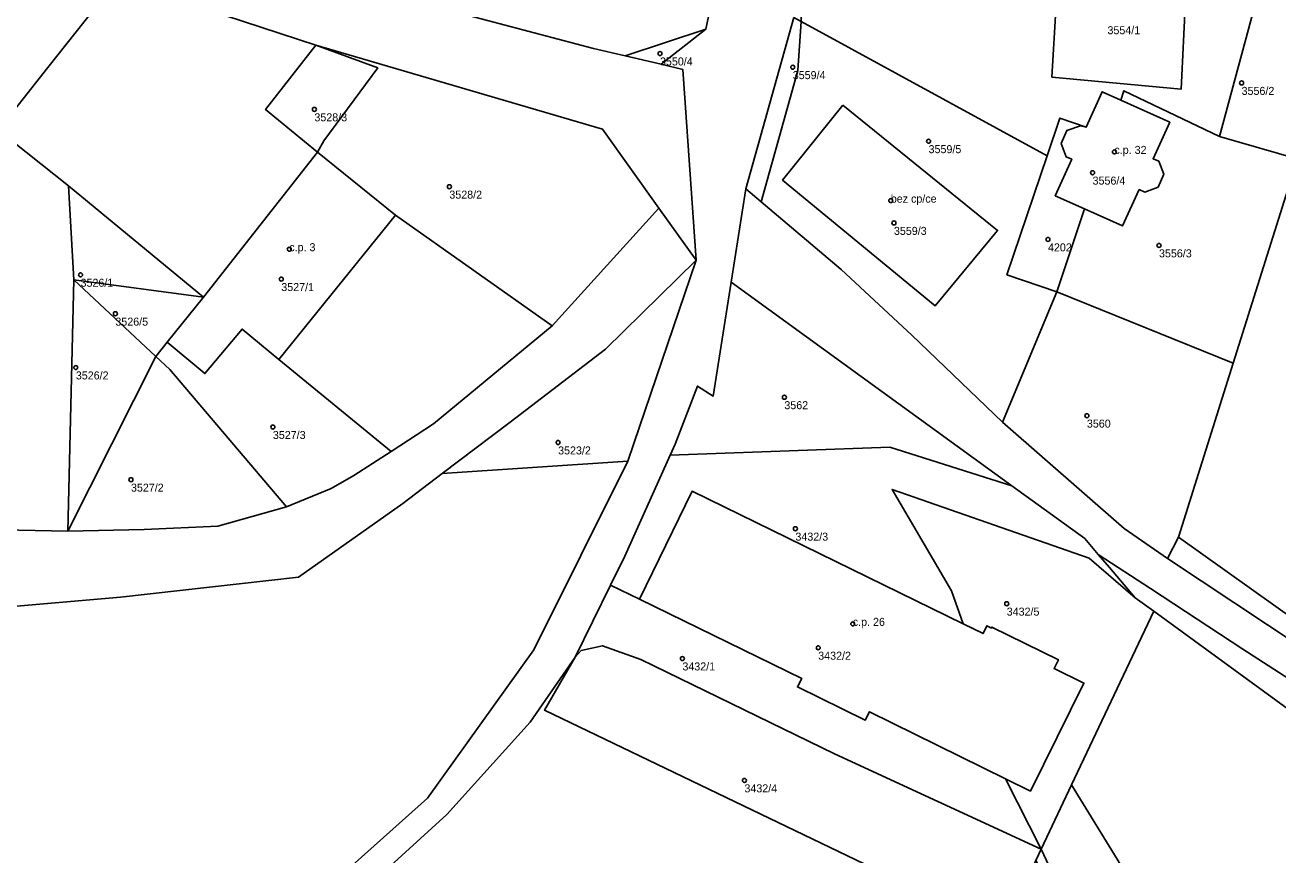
# Model space of a CAD drawing. Extents: x -878211 to -870363, y -1058464 to -1052522.
# Drawn here: x -876248.4 to -876091.8, y -1055083.2 to -1054979.5 of the extents above; entities that cross this region are included whole.
import ezdxf

# ---------------------------------------------------------------- set-up
doc = ezdxf.new("R2010")
doc.units = 0
for name, color, linetype in [('Vrstva 50', 7, 'Continuous'), ('Vrstva 51', 7, 'Continuous'), ('Vrstva 52', 7, 'Continuous')]:
    doc.layers.add(name, color=color, linetype=linetype)

msp = doc.modelspace()

# ---------------------------------------------------------------- linework, layer by layer
at = {"layer": 'Vrstva 50'}
for centre in [(-876169.04, -1054983.06994), (-876152.45, -1054984.77994), (-876096.37, -1054986.74994), (-876212.22, -1054990.04994), (-876135.48, -1054994.02994), (-876112.26, -1054995.35994), (-876114.99, -1054997.95994), (-876195.36, -1054999.70994), (-876140.2, -1055001.44994), (-876139.81, -1055004.23994), (-876120.56, -1055006.29994), (-876106.69, -1055007.04994), (-876215.36, -1055007.51994), (-876241.44, -1055010.71994), (-876216.36, -1055011.25994), (-876237.09, -1055015.57994), (-876242.03, -1055022.29994), (-876153.5, -1055026.01994), (-876115.7, -1055028.31994), (-876217.41, -1055029.73994), (-876181.77, -1055031.66994), (-876235.14, -1055036.31994), (-876152.12, -1055042.43994), (-876125.72, -1055051.80994), (-876144.95, -1055054.32994), (-876149.27, -1055057.31994), (-876166.24, -1055058.65994), (-876158.49, -1055073.88994)]:
    msp.add_circle(centre, 0.25, dxfattribs=at)
at = {"layer": 'Vrstva 51'}
for points in [[(-876192.82, -1054978.37), (-876177.34, -1054982.44), (-876173.38, -1054983.37), (-876163.32, -1054980.03), (-876160.81, -1054968.12), (-876164.19, -1054966.37), (-876185.22, -1054958.74), (-876186.64, -1054962)], [(-876111.56, -1054967.55), (-876117.63, -1054967.56), (-876121.09, -1054967.32), (-876123.64, -1054966.96), (-876133.24, -1054967.48), (-876126.34, -1054969.03), (-876126.76, -1054976.42), (-876119.52, -1054976.93), (-876120.07, -1054986.02), (-876103.91, -1054987.52), (-876103.39, -1054976.34), (-876104.13, -1054976.31), (-876104.06, -1054973.91), (-876109.76, -1054973.6), (-876109.46, -1054967.74)], [(-876230.61, -1055019.14), (-876225.89, -1055023.06), (-876221.26, -1055017.49), (-876216.66, -1055021.3), (-876202.64, -1055032.79), (-876197.32, -1055029.35), (-876182.5, -1055017.11), (-876202.1, -1055003.26), (-876211.84, -1054995.38), (-876218.33, -1054990.08), (-876212.05, -1054982.01), (-876236.87, -1054973.88), (-876237.48, -1054974.65), (-876245.51, -1054984.81), (-876251.72, -1054992.65), (-876242.95, -1054999.62), (-876226.09, -1055013.5)], [(-876089.29, -1054996.25), (-876083.43, -1054979.02), (-876094.37, -1054975.83), (-876099.15, -1054993.44)], [(-876152.32, -1054978.56), (-876158.32, -1054999.97), (-876156.39, -1055001.61), (-876151.83, -1054985.19), (-876151.42, -1054979.05)], [(-876163.32, -1054980.03), (-876173.38, -1054983.37), (-876168.91, -1054984.41)], [(-876126.23, -1055029.14), (-876119.47, -1055012.84), (-876125.7, -1055010.71), (-876120.67, -1054995.87), (-876151.42, -1054979.05), (-876151.83, -1054985.19), (-876156.39, -1055001.61), (-876146.41, -1055010.04), (-876137.56, -1055018.26)], [(-876212.05, -1054982.01), (-876218.33, -1054990.08), (-876211.84, -1054995.38), (-876211.03, -1054993.98), (-876204.31, -1054984.86)], [(-876204.31, -1054984.86), (-876211.03, -1054993.98), (-876211.84, -1054995.38), (-876202.1, -1055003.26), (-876182.5, -1055017.11), (-876169.19, -1055002.37), (-876176.22, -1054992.51), (-876212.05, -1054982.01)], [(-876097.42, -1055021.74), (-876104.26, -1055043.49), (-876053.74, -1055079.5), (-876016.38, -1055109.9), (-875979.71, -1055134.31), (-875976.33, -1055133.07), (-875966.79, -1055136.01), (-875949.8, -1055118.58), (-875906.55, -1055032.87), (-875978.7, -1054987.87), (-875998.96, -1054984.29), (-876051.39, -1054986.14), (-876052.15, -1054989.95), (-876052.67, -1054991.22), (-876056.06, -1054997.03), (-876063.41, -1055005.05), (-876067.92, -1055003.02), (-876087.78, -1054996.68), (-876089.29, -1054996.25), (-876090.8, -1055000.71)], [(-876115.77, -1054992.27), (-876116.51, -1054992.09), (-876118.19, -1054992.68), (-876118.91, -1054994.3), (-876118.29, -1054995.96), (-876117.6, -1054996.28), (-876119.66, -1055000.83), (-876116, -1055002.47), (-876111.23, -1055004.61), (-876109.15, -1055000.07), (-876108.47, -1055000.38), (-876106.81, -1054999.76), (-876106.08, -1054998.16), (-876106.73, -1054996.52), (-876107.42, -1054996.21), (-876105.35, -1054991.65), (-876111.46, -1054988.9), (-876113.8, -1054987.85)], [(-876116, -1055002.47), (-876119.47, -1055012.84), (-876097.42, -1055021.74), (-876090.8, -1055000.71), (-876089.29, -1054996.25), (-876099.15, -1054993.44), (-876111.07, -1054987.72), (-876111.46, -1054988.9), (-876105.35, -1054991.65), (-876107.42, -1054996.21), (-876106.73, -1054996.52), (-876106.08, -1054998.16), (-876106.81, -1054999.76), (-876108.47, -1055000.38), (-876109.15, -1055000.07), (-876111.23, -1055004.61)], [(-876146.18, -1054989.51), (-876153.73, -1054998.89), (-876134.65, -1055014.58), (-876126.85, -1055005.18)], [(-876146.18, -1054989.51), (-876126.85, -1055005.18), (-876134.65, -1055014.58), (-876153.73, -1054998.89)], [(-876125.7, -1055010.71), (-876119.47, -1055012.84), (-876116, -1055002.47), (-876119.66, -1055000.83), (-876117.6, -1054996.28), (-876118.29, -1054995.96), (-876118.91, -1054994.3), (-876118.19, -1054992.68), (-876116.51, -1054992.09), (-876115.77, -1054992.27), (-876119.06, -1054991.14), (-876120.67, -1054995.87)], [(-876226.09, -1055013.5), (-876242.95, -1054999.62), (-876242.26, -1055011.34)], [(-876196.25, -1055035.56), (-876173.05, -1055033.99), (-876164.53, -1055008.9), (-876175.86, -1055020.02), (-876187.78, -1055029.12)], [(-876243.04, -1055042.76), (-876232.03, -1055020.91), (-876242.26, -1055011.34)], [(-876230.61, -1055019.14), (-876226.09, -1055013.5), (-876242.26, -1055011.34), (-876232.03, -1055020.91)], [(-876167.76, -1055033.27), (-876140.32, -1055032.25), (-876125.07, -1055037.07), (-876160.15, -1055011.62), (-876162.39, -1055025.86), (-876164.37, -1055024.61), (-876167.13, -1055031.87)], [(-876097.42, -1055021.74), (-876119.47, -1055012.84), (-876126.23, -1055029.14), (-876111.06, -1055042.43), (-876105.63, -1055046.16), (-876104.26, -1055043.49)], [(-876232.03, -1055020.91), (-876230.27, -1055022.56), (-876215.72, -1055039.69), (-876210.13, -1055037.4), (-876207.31, -1055035.81), (-876202.64, -1055032.79), (-876216.66, -1055021.3), (-876221.26, -1055017.49), (-876225.89, -1055023.06), (-876230.61, -1055019.14)], [(-876243.04, -1055042.76), (-876233.48, -1055042.54), (-876224.27, -1055042.14), (-876215.72, -1055039.69), (-876230.27, -1055022.56), (-876232.03, -1055020.91)], [(-876109.68, -1055051.07), (-876112.89, -1055047.29), (-876114.28, -1055045.66), (-876115.97, -1055043.68), (-876125.07, -1055037.07), (-876140.32, -1055032.25), (-876167.76, -1055033.27), (-876173.43, -1055045.89), (-876175.21, -1055049.49), (-876171.58, -1055051.26), (-876165.03, -1055037.75), (-876131.14, -1055054.33), (-876132.63, -1055050.21), (-876140.05, -1055037.54), (-876115.43, -1055046.11)], [(-876171.58, -1055051.26), (-876151.33, -1055061.14), (-876151.86, -1055062.2), (-876143.4, -1055066.36), (-876142.88, -1055065.31), (-876125.86, -1055073.69), (-876122.75, -1055075.22), (-876116.08, -1055061.72), (-876119.79, -1055059.9), (-876119.26, -1055058.82), (-876127.56, -1055054.73), (-876127.63, -1055054.86), (-876128.19, -1055054.57), (-876128.66, -1055055.54), (-876131.14, -1055054.33), (-876165.03, -1055037.75)], [(-876125.86, -1055073.69), (-876121.4, -1055082.49), (-876117.61, -1055074.46), (-876107.35, -1055052.74), (-876109.68, -1055051.07), (-876115.43, -1055046.11), (-876140.05, -1055037.54), (-876132.63, -1055050.21), (-876131.14, -1055054.33), (-876128.66, -1055055.54), (-876128.19, -1055054.57), (-876127.63, -1055054.86), (-876127.56, -1055054.73), (-876119.26, -1055058.82), (-876119.79, -1055059.9), (-876116.08, -1055061.72), (-876122.75, -1055075.22)], [(-875977.58, -1055142.97), (-875979.71, -1055134.31), (-876016.38, -1055109.9), (-876053.74, -1055079.5), (-876104.26, -1055043.49), (-876105.63, -1055046.16), (-876055.78, -1055079.24), (-876034.65, -1055095.81), (-875993.71, -1055132)], [(-876179.64, -1055058.47), (-876178.87, -1055057.67), (-876176.24, -1055057.07), (-876171.43, -1055058.8), (-876147.22, -1055070.55), (-876121.4, -1055082.49), (-876125.86, -1055073.69), (-876142.88, -1055065.31), (-876143.4, -1055066.36), (-876151.86, -1055062.2), (-876151.33, -1055061.14), (-876171.58, -1055051.26), (-876175.21, -1055049.49)], [(-876026.71, -1055116.15), (-876054.99, -1055090.93), (-876107.35, -1055052.74), (-876117.61, -1055074.46), (-876096.34, -1055109.09), (-876070.12, -1055147.03), (-876039.02, -1055184.03), (-875996.85, -1055230.09), (-875978.11, -1055212.67), (-875964.02, -1055196.27), (-875956.01, -1055187.77), (-875992.23, -1055151.65), (-876009.21, -1055134.73)], [(-876122.07, -1055083.91), (-876121.4, -1055082.49), (-876147.22, -1055070.55), (-876171.43, -1055058.8), (-876176.24, -1055057.07), (-876178.87, -1055057.67), (-876179.64, -1055058.47), (-876183.47, -1055065.11), (-876126.19, -1055092.63), (-876123.62, -1055087.19)], [(-876109.86, -1055107.03), (-876121.4, -1055082.49), (-876122.07, -1055083.91)]]:
    msp.add_lwpolyline(points, close=True, dxfattribs=at)
for points in [[(-876285.26, -1054964.19), (-876245.2, -1054971.07), (-876236.87, -1054973.88), (-876212.05, -1054982.01), (-876176.22, -1054992.51), (-876169.19, -1055002.37), (-876164.53, -1055008.9), (-876166.19, -1054985.05), (-876168.91, -1054984.41), (-876173.38, -1054983.37), (-876177.34, -1054982.44), (-876192.82, -1054978.37), (-876212.54, -1054973.01), (-876229.54, -1054968.31), (-876238.66, -1054965.79), (-876247.95, -1054964.03), (-876267.26, -1054960.95)], [(-876275.67, -1055042.1), (-876243.04, -1055042.76), (-876242.26, -1055011.34), (-876242.95, -1054999.62), (-876251.72, -1054992.65), (-876245.51, -1054984.81), (-876237.48, -1054974.65), (-876236.87, -1054973.88), (-876245.2, -1054971.07), (-876285.26, -1054964.19)], [(-876089.25, -1054972.56), (-876109.46, -1054967.74), (-876109.76, -1054973.6), (-876104.06, -1054973.91), (-876104.13, -1054976.31), (-876103.39, -1054976.34), (-876103.91, -1054987.52), (-876120.07, -1054986.02), (-876119.52, -1054976.93), (-876126.76, -1054976.42), (-876126.34, -1054969.03), (-876133.24, -1054967.48), (-876141.85, -1054968.66), (-876151.7, -1054970.15), (-876151.42, -1054979.05), (-876120.67, -1054995.87), (-876119.06, -1054991.14), (-876115.77, -1054992.27), (-876113.8, -1054987.85), (-876111.46, -1054988.9), (-876111.07, -1054987.72), (-876099.15, -1054993.44), (-876094.37, -1054975.83), (-876083.43, -1054979.02)], [(-876160.81, -1054968.12), (-876163.32, -1054980.03), (-876168.91, -1054984.41), (-876166.19, -1054985.05), (-876164.53, -1055008.9), (-876173.05, -1055033.99), (-876184.79, -1055057.57), (-876198.09, -1055076.1), (-876221.24, -1055096.79)], [(-876219.13, -1055099.52), (-876195.69, -1055078.15), (-876185.26, -1055066.62), (-876179.64, -1055058.47), (-876175.21, -1055049.49), (-876173.43, -1055045.89), (-876167.76, -1055033.27), (-876167.13, -1055031.87), (-876164.37, -1055024.61), (-876162.39, -1055025.86), (-876160.15, -1055011.62), (-876158.32, -1054999.97), (-876152.32, -1054978.56)], [(-876034.65, -1055095.81), (-876055.78, -1055079.24), (-876105.63, -1055046.16), (-876111.06, -1055042.43), (-876126.23, -1055029.14), (-876137.56, -1055018.26), (-876146.41, -1055010.04), (-876156.39, -1055001.61), (-876158.32, -1054999.97), (-876160.15, -1055011.62), (-876125.07, -1055037.07), (-876115.97, -1055043.68), (-876114.28, -1055045.66), (-876107.77, -1055049.92), (-876096.22, -1055057.5), (-876084.72, -1055064.92), (-876071.96, -1055073.05), (-876063.43, -1055078.72), (-876056.15, -1055083.98)], [(-876251.86, -1055052.34), (-876236.43, -1055051), (-876214.2, -1055048.51), (-876201.17, -1055039.3), (-876196.25, -1055035.56), (-876187.78, -1055029.12), (-876175.86, -1055020.02), (-876164.53, -1055008.9), (-876169.19, -1055002.37), (-876182.5, -1055017.11), (-876197.32, -1055029.35), (-876202.64, -1055032.79), (-876207.31, -1055035.81), (-876210.13, -1055037.4), (-876215.72, -1055039.69), (-876224.27, -1055042.14), (-876233.48, -1055042.54), (-876243.04, -1055042.76), (-876275.67, -1055042.1)], [(-876253.17, -1055110.11), (-876221.24, -1055096.79), (-876198.09, -1055076.1), (-876184.79, -1055057.57), (-876173.05, -1055033.99), (-876196.25, -1055035.56), (-876201.17, -1055039.3), (-876214.2, -1055048.51), (-876236.43, -1055051), (-876251.86, -1055052.34)], [(-876056.15, -1055083.98), (-876063.43, -1055078.72), (-876071.96, -1055073.05), (-876084.72, -1055064.92), (-876096.22, -1055057.5), (-876107.77, -1055049.92), (-876114.28, -1055045.66), (-876112.89, -1055047.29), (-876109.68, -1055051.07), (-876107.35, -1055052.74), (-876054.99, -1055090.93)], [(-876126.19, -1055092.63), (-876183.47, -1055065.11), (-876179.64, -1055058.47), (-876185.26, -1055066.62), (-876195.69, -1055078.15), (-876219.13, -1055099.52)], [(-875926.78, -1055320.5), (-875968, -1055264.33), (-875996.85, -1055230.09), (-876039.02, -1055184.03), (-876070.12, -1055147.03), (-876096.34, -1055109.09), (-876117.61, -1055074.46), (-876121.4, -1055082.49), (-876109.86, -1055107.03), (-876098.18, -1055124.7), (-876075.88, -1055149.38), (-876071.16, -1055154.15), (-876067.83, -1055161.11), (-876059.77, -1055177.68), (-876024.99, -1055217.16), (-875969.68, -1055294.51)]]:
    msp.add_lwpolyline(points, dxfattribs=at)
at = {"layer": 'Vrstva 52'}
for points in [[(-876113.8, -1054987.85), (-876115.77, -1054992.27), (-876116.51, -1054992.09), (-876118.19, -1054992.68), (-876118.91, -1054994.3), (-876118.29, -1054995.96), (-876117.6, -1054996.28), (-876119.66, -1055000.83), (-876116, -1055002.47), (-876111.23, -1055004.61), (-876109.15, -1055000.07), (-876108.47, -1055000.38), (-876106.81, -1054999.76), (-876106.08, -1054998.16), (-876106.73, -1054996.52), (-876107.42, -1054996.21), (-876105.35, -1054991.65), (-876111.46, -1054988.9)], [(-876146.18, -1054989.51), (-876153.73, -1054998.89), (-876134.65, -1055014.58), (-876126.85, -1055005.18)], [(-876226.09, -1055013.5), (-876230.61, -1055019.14), (-876225.89, -1055023.06), (-876221.26, -1055017.49), (-876216.66, -1055021.3), (-876202.1, -1055003.26), (-876211.84, -1054995.38)], [(-876171.58, -1055051.26), (-876151.33, -1055061.14), (-876151.86, -1055062.2), (-876143.4, -1055066.36), (-876142.88, -1055065.31), (-876125.86, -1055073.69), (-876122.75, -1055075.22), (-876116.08, -1055061.72), (-876119.79, -1055059.9), (-876119.26, -1055058.82), (-876127.56, -1055054.73), (-876127.63, -1055054.86), (-876128.19, -1055054.57), (-876128.66, -1055055.54), (-876131.14, -1055054.33), (-876165.03, -1055037.75)]]:
    msp.add_lwpolyline(points, close=True, dxfattribs=at)

# ---------------------------------------------------------------- texts
at = {"layer": 'Vrstva 50'}
for s, p in [('3554/1', (-876113.13, -1054980.659)), ('3550/4', (-876169.04, -1054984.559)), ('3559/4', (-876152.45, -1054986.269)), ('3556/2', (-876096.37, -1054988.239)), ('3528/3', (-876212.22, -1054991.539)), ('3559/5', (-876135.48, -1054995.519)), ('c.p. 32', (-876112.26, -1054995.61)), ('3556/4', (-876114.99, -1054999.449)), ('3528/2', (-876195.36, -1055001.199)), ('bez cp/ce', (-876140.2, -1055001.7)), ('3559/3', (-876139.81, -1055005.729)), ('c.p. 3', (-876215.36, -1055007.77)), ('4202', (-876120.56, -1055007.789)), ('3556/3', (-876106.69, -1055008.539)), ('3526/1', (-876241.44, -1055012.209)), ('3527/1', (-876216.36, -1055012.749)), ('3526/5', (-876237.09, -1055017.069)), ('3526/2', (-876242.03, -1055023.789)), ('3562', (-876153.5, -1055027.509)), ('3560', (-876115.7, -1055029.809)), ('3527/3', (-876217.41, -1055031.229)), ('3523/2', (-876181.77, -1055033.159)), ('3527/2', (-876235.14, -1055037.809)), ('3432/3', (-876152.12, -1055043.929)), ('3432/5', (-876125.72, -1055053.299)), ('c.p. 26', (-876144.95, -1055054.58)), ('3432/2', (-876149.27, -1055058.809)), ('3432/1', (-876166.24, -1055060.149)), ('3432/4', (-876158.49, -1055075.379))]:
    msp.add_text(s, height=0.999996, dxfattribs=at).set_placement(p)

doc.saveas('drawing.dxf')
